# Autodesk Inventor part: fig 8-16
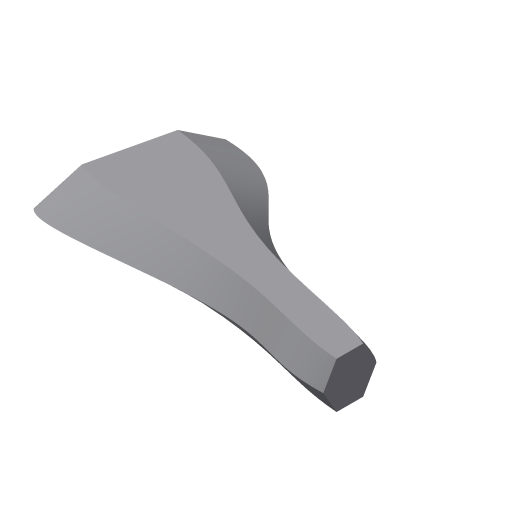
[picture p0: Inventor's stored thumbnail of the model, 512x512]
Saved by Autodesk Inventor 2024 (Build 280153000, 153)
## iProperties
Created: 2004-05
Part Number: fig 8-16
Document SubType Name: Modeling
Designer: CADCIM Technologies
Manufacturer: Standard
Standards Organization: Custom
Density: 1 g/cm^3
Material: Generic
Appearance: Default
Author: CADCIM Technologies
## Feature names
1. Sweep7
## Parameters: d6 = 0, d7 = 0
